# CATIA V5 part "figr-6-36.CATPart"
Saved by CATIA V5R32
Part number: Part1
Bounding box of the stored display mesh (mm): x -79 to 0, y -87.239 to 111.436, z 0 to 82.954
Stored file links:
  D:\PROJECTS\Project 2022\CATIA V5 6R 2022\Resources\Part Files\c06_catia_v5_6r2022_prt\figr-6-36.CATPart
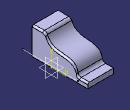
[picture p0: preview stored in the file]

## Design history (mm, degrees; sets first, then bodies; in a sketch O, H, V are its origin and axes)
Body1 (main body)
  Sketch1 on yz-plane, origin (0, 0, 0), H (0, 1, 0), V (0, 0, 1)
    line L1 (111.4359, 0) -> (-58.1761, 0)
    line L2 (-58.1761, 0) -> (-58.1761, 82.9535)
    point P2 (111.4359, 0)
    line L3 (-58.1761, 82.9535) -> (-18.8251, 82.9535)
    point P4 (-18.8251, 82.9535)
    spline S1 through (-18.8251, 82.9535) (0, 57.9624) (68.0293, 40.7554) (77.8618, 15.3546)
    line L4 (77.8618, 15.3546) -> (111.4359, 15.3546)
    line L5 (111.4359, 15.3546) -> (111.4359, 0)
    point P6 (77.8618, 15.3546)
    point P7 (-18.8251, 82.9535)
    point P8 (0, 57.9624)
    point P9 (77.8618, 15.3546)
    horizontal: L1 H, L3 H, L4 H
    vertical: L2 V, L5 V
    coincidence: P2 H, P7 P4, P8 V, P9 P6
  Pad1: profile Sketch1, direction (-1, 0, 0), length 79
  Sketch2 on yz-plane, origin (0, 0, 0), H (0, 1, 0), V (0, 0, 1)
    line L1 (-87.2393, 4.8989) -> (80.7003, 4.8989)
  Fillet1: radius 10, on edge [face of Pad1 from Sketch1.S1 | face of Pad1 from Sketch1.L3]; edge [face of Pad1 from Sketch1.L4 | face of Pad1 from Sketch1.S1]
  Fillet2: radius 5, on edge [face of Pad1 from Sketch1.S1 | start face of Pad1]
